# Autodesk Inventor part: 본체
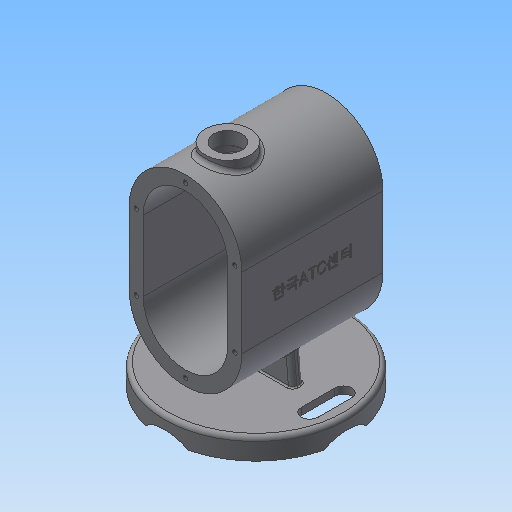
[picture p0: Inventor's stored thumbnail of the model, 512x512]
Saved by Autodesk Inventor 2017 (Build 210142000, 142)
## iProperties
Created: 2016-12
Part Number: 본체
Material: 일반
Document SubType Name: Modeling
Designer: mduedu
Density: 1 g/cm^3
Appearance: 기본값
Mass: 405.481 g
Surface Area: 1080.89 cm^2
Volume: 405.481 cm^3
Author: mduedu
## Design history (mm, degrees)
sketch "스케치1"
  geometry: L1 (40, -25)-(40, 25); L2 (-40, 25)-(-40, -25); L3 (-40, -25)-(40, 25); L4 (40, -25)-(-40, 25); L5 (0, 25)-(0, -25); A1 r 40 centre (0, 25) between (40, 25) and (-40, 25); A2 r 40 centre (0, -25) between (-40, -25) and (40, -25); 1 further point
  constraints: 10 end point, 4 point on circle, 3 tangent, 2 centre point, 2 midpoint, 2 parallel, 1 vertical
  dimensions: "d0" = 130 dimension on A2 A1; "d2" = 80 distance between parallel lines of L1 L2
extrude "돌출1" new body sketch "스케치1" stored distance "d3" = 100; taper "d4" = 0 deg
feature "쉘1" dims "d5" = 10
sketch "스케치2"
  geometry: L1 (-75, 65)-(-90, 65); L2 (-90, 65)-(-90, 0); L3 (-75, 0)-(-75, 65); L4 (-75, 0)-(-90, 0); 1 further point
  constraints: 8 end point, 1 horizontal, 1 horizontal alignment, 1 parallel, 1 perpendicular
  dimensions: "d6" = 90 distance from line of L2 point (0, 0); "d83" = 15 distance of L1.start L1.end; "d84" = 130 diameter of L1 L4
revolve "회전1" sketch "스케치2" stored, may be unused: angle "d85" = 90 deg
fillet "모깎기5" dims "d86" = 3
hole "구멍6" diameter "d89" = 120; stored, may be unused: countersink angle "d93" = 90 deg, drill point angle "d95" = 0 deg; dims "d87" = 10, "d88" = 10, "d90" = 6, "d91" = 4, "d92" = 2, "d94" = 10
sketch "스케치15"
  geometry: L1 (-90, -60)-(-90, 60) reference; A1 r 21.75 centre (-105.75, 0) between (-90, -15) and (-90, 15); 3 further points
  constraints: 3 point on circle, 2 point on line, 1 centre point, 1 horizontal alignment, 1 midpoint
  dimensions: "d119" = 30 distance of A1.start A1.end; "d120" = 6 distance of point (-84, 0) point (-90, 0)
extrude "돌출6" cut sketch "스케치15" stored distance "d97" = 10; taper "d98" = 0 deg
sketch "스케치5"
  geometry: L1 (4, -30)-(-4, -30); L2 (-4, -30)-(-4, 30); L3 (-4, 30)-(4, 30); L4 (4, 30)-(4, -30); L5 (4, -30)-(-4, 30); L6 (-4, -30)-(4, 30); 3 further points
  constraints: 12 end point, 3 midpoint, 2 parallel, 1 coincident, 1 horizontal, 1 perpendicular
  dimensions: "d22" = 8 distance of L2.end L3.end; "d24" = 60 distance of L1.end L2.end
extrude "돌출3" join sketch "스케치5" stored distance "d25" = 80; taper "d26" = 0 deg
feature "면 기울기1" dims angle "d27" = 5 deg
sketch "스케치6"
  geometry: L1 (-28.115, -53.453)-(-30, -75); L2 (-62, -75)-(62, -75) reference; A1 r 40 centre (0, -25) between (-40, -25) and (40, -25) reference; 1 further point
  constraints: 2 end point, 1 point on circle, 1 point on line
  dimensions: "d28" = 30 horizontal distance of A1.centre L1.end; "d102" = 85 deg angle of L2 L1
feature "리브1" sketch "스케치6" dims "d30" = 1, "d31" = 8, "d32" = 0, "d33" = 0, "d34" = 1, "d35" = 1
fillet "모깎기2" dims "d36" = 3
fillet "모깎기3" dims "d37" = 1, "d38" = 1
node "작업 평면1"
sketch "스케치9"
  geometry: 1 further point
sketch "스케치7"
  geometry: L1 (40, 50)-(-40, 50) reference; C1 r 16 at (0, 20); 1 further point
  constraints: 1 centre point, 1 vertical alignment
  dimensions: "d40" = 32 diameter of C1; "d41" = 30 distance from line of C1.centre L1
extrude "돌출4" join sketch "스케치7" stored distance "d42" = 80; taper "d43" = 0 deg
hole "구멍2" diameter "d46" = 20; stored, may be unused: countersink angle "d50" = 90 deg, drill point angle "d52" = 118 deg; dims "d44" = 10, "d45" = 10, "d47" = 6, "d48" = 4, "d49" = 2, "d51" = 8
fillet "모깎기4" dims "d53" = 3
node "작업 평면2"
sketch "스케치8"
  geometry: C1 r 16 at (0, 0) reference; C2 r 15 at (0, 0); 1 further point
  constraints: 1 centre point, 1 coincident
  dimensions: "d55" = 30 diameter of C2
extrude "돌출5" cut sketch "스케치8" stored distance "d56" = 80; taper "d57" = 0 deg
chamfer "모따기1" distance "d58" = 1; stored, may be unused: second distance "d59" = 2, angle "d60" = 45 deg
sketch "스케치10"
  geometry: 2 further points
  constraints: 1 coincident, 1 other
feature "엠보싱1" sketch "스케치10" dims "d0" = 130, "d2" = 80, "d61" = 0.5, "d62" = 0
sketch "스케치11"
  geometry: 1 further point
hole "구멍3" sketch "스케치11" at (0, 60) diameter "d63" = 3.242; stored, may be unused: countersink angle "d67" = 90 deg, drill point angle "d69" = 120 deg; dims "d64" = 8.6, "d65" = 4, "d66" = 2, "d68" = 10.6
sketch "스케치12"
  geometry: 1 further point
hole "구멍5" sketch "스케치12" at (0, 60) diameter "d70" = 3.242; stored, may be unused: countersink angle "d74" = 90 deg, drill point angle "d76" = 120 deg; dims "d71" = 8.6, "d72" = 4, "d73" = 2, "d75" = 10.6
sketch "스케치16"
  geometry: L1 (0, 0)-(0, 50); L2 (-56, 12)-(-56, -12); L3 (-44, 12)-(-44, -12); L4 (-50, -12)-(-50, 12); A1 r 50 centre (0, 0) between (0, 50) and (-50, 0); A2 r 6 centre (-50, 12) between (-44, 12) and (-56, 12); A3 r 6 centre (-50, -12) between (-56, -12) and (-44, -12); 1 further point
  constraints: 8 end point, 6 point on circle, 4 tangent, 3 centre point, 3 parallel, 1 coincident, 1 equal radius, 1 horizontal alignment, 1 midpoint, 1 vertical
  dimensions: "d103" = 100 diameter of A1; "d121" = 6 radius of A2; "d122" = 24 distance of L4.start L4.end
extrude "돌출7" cut sketch "스케치16" stored distance "d123" = 10; taper "d124" = 0 deg
node "솔리드1"
pattern_circular "원형 패턴1" dims angle "d100" = 90 deg
mirror "대칭1"
pattern_linear "직사각형 패턴1"
pattern_linear "직사각형 패턴2"
mirror "대칭2"
sketch "스케치13"
  geometry: L1 (-40, 25)-(-40, -25) reference; L2 (40, -25)-(40, 25) reference; L3 (35, 25)-(35, -25); L4 (-35, -25)-(-35, 25); A1 r 40 centre (0, 25) between (40, 25) and (-40, 25) reference; A2 r 40 centre (0, -25) between (-40, -25) and (40, -25) reference; A3 r 35 centre (0, 25) between (35, 25) and (-35, 25); A4 r 35 centre (0, -25) between (-35, -25) and (35, -25); 2 further points
  constraints: 5 point on circle, 4 end point, 2 centre point, 3 other
  dimensions: "d77" = 5 distance between parallel lines of L3 L2
sketch "스케치14"
  geometry: L1 (-40, 25)-(-40, -25) reference; L2 (40, -25)-(40, 25) reference; L3 (35, 25)-(35, -25); L4 (-35, -25)-(-35, 25); A1 r 40 centre (0, 25) between (40, 25) and (-40, 25) reference; A2 r 40 centre (0, -25) between (-40, -25) and (40, -25) reference; A3 r 35 centre (0, 25) between (35, 25) and (-35, 25); A4 r 35 centre (0, -25) between (-35, -25) and (35, -25); 2 further points
  constraints: 5 point on circle, 4 end point, 2 centre point, 3 other
  dimensions: "d80" = 5 distance between parallel lines of L2 L3
